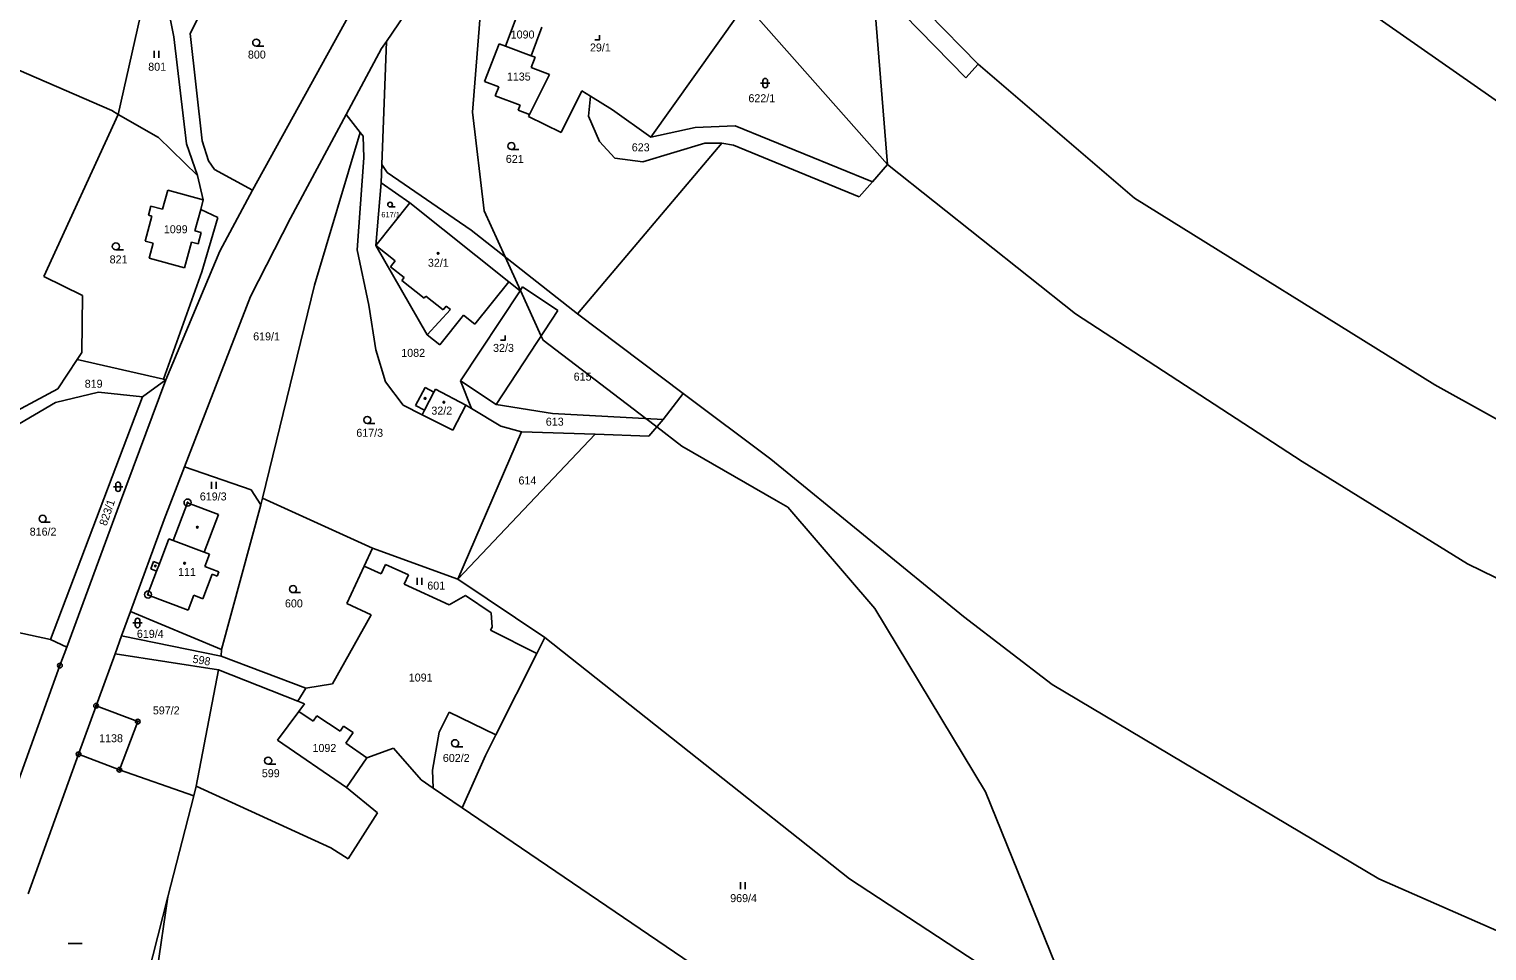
# Model space of a CAD drawing. Extents: x -547623 to -538651, y -1096714 to -1086522.
# Drawn here: x -542658.7 to -542349, y -1093298.3 to -1093102.4 of the extents above; entities that cross this region are included whole.
import ezdxf

# ---------------------------------------------------------------- set-up
doc = ezdxf.new("R2010")
doc.units = 0
for name, color, linetype in [('Vrstva 1', 7, 'Continuous'), ('Vrstva 25', 7, 'Continuous'), ('Vrstva 33', 7, 'Continuous'), ('Vrstva 52', 7, 'Continuous'), ('Vrstva 83', 7, 'Continuous'), ('Vrstva 86', 7, 'Continuous'), ('Vrstva 90', 7, 'Continuous'), ('Vrstva 92', 7, 'Continuous')]:
    doc.layers.add(name, color=color, linetype=linetype)

msp = doc.modelspace()

# ---------------------------------------------------------------- linework, layer by layer
at = {"layer": 'Vrstva 1'}
for points in [[(-542582.78, -1093104.99), (-542568.37, -1093083.76)], [(-542639.74, -1093120.53), (-542632.71, -1093089.02)], [(-542478.44, -1093087.92), (-542457.08, -1093109.85)], [(-542618.31, -1093091.02), (-542624.48, -1093103.34)], [(-542479.46, -1093092.45), (-542459.67, -1093112.74)], [(-542479.46, -1093092.45), (-542476.32, -1093131.19)], [(-542629.74, -1093094.66), (-542627.95, -1093104.03)], [(-542589.06, -1093096.44), (-542611.21, -1093136.61)], [(-542506.5, -1093097.1), (-542476.32, -1093131.19)], [(-542374.27, -1093098.54), (-542322.4, -1093134.78)], [(-542557.5, -1093105.98), (-542555.23, -1093099.95)], [(-542526.63, -1093125.33), (-542508, -1093099.2)], [(-542627.95, -1093104.03), (-542625.23, -1093126.8)], [(-542624.48, -1093103.34), (-542621.93, -1093126.14)], [(-542583.81, -1093106.51), (-542582.78, -1093104.99)], [(-542583.77, -1093131.16), (-542582.78, -1093104.99)], [(-542549.78, -1093102), (-542552.05, -1093108.03)], [(-542641.11, -1093119.69), (-542668.96, -1093107.67)], [(-542591.32, -1093120.51), (-542583.81, -1093106.51)], [(-542561.96, -1093113.49), (-542558.83, -1093105.48)], [(-542558.83, -1093105.48), (-542557.5, -1093105.98)], [(-542557.5, -1093105.98), (-542552.05, -1093108.03)], [(-542552.05, -1093108.03), (-542551.15, -1093108.37)], [(-542551.15, -1093108.37), (-542552, -1093110.55)], [(-542552, -1093110.55), (-542548.17, -1093112.05)], [(-542459.67, -1093112.74), (-542457.08, -1093109.85)], [(-542457.08, -1093109.85), (-542423.87, -1093138.3)], [(-542558.93, -1093114.65), (-542561.96, -1093113.49)], [(-542552.4, -1093120.52), (-542548.17, -1093112.05)], [(-542559.66, -1093116.54), (-542558.93, -1093114.65)], [(-542554.36, -1093118.57), (-542559.66, -1093116.54)], [(-542545.69, -1093124.39), (-542541.25, -1093115.51)], [(-542541.25, -1093115.51), (-542539.46, -1093116.62)], [(-542539.46, -1093116.62), (-542539.83, -1093120.87)], [(-542539.46, -1093116.62), (-542534.78, -1093119.51)], [(-542639.74, -1093120.53), (-542641.11, -1093119.69)], [(-542554.76, -1093119.61), (-542554.36, -1093118.57)], [(-542552.4, -1093120.52), (-542554.76, -1093119.61)], [(-542526.63, -1093125.33), (-542534.78, -1093119.51)], [(-542639.74, -1093120.53), (-542655.54, -1093154.96)], [(-542631.19, -1093125.39), (-542639.74, -1093120.53)], [(-542603.16, -1093142.57), (-542591.32, -1093120.51)], [(-542588.34, -1093124.34), (-542591.32, -1093120.51)], [(-542552.62, -1093120.95), (-542552.4, -1093120.52)], [(-542552.62, -1093120.95), (-542545.69, -1093124.39)], [(-542539.83, -1093120.87), (-542537.51, -1093126.26)], [(-542526.63, -1093125.33), (-542517.16, -1093123.27)], [(-542517.16, -1093123.27), (-542508.71, -1093122.95)], [(-542508.71, -1093122.95), (-542479.54, -1093134.83)], [(-542622.93, -1093133.52), (-542631.19, -1093125.39)], [(-542621.93, -1093126.14), (-542620.54, -1093130.39)], [(-542588.34, -1093124.34), (-542598.04, -1093156.8)], [(-542587.71, -1093125.15), (-542588.34, -1093124.34)], [(-542587.57, -1093129.75), (-542587.71, -1093125.15)], [(-542542.18, -1093162.93), (-542511.53, -1093126.62)], [(-542537.51, -1093126.26), (-542534.27, -1093129.8)], [(-542528.29, -1093130.61), (-542515.15, -1093126.64)], [(-542515.15, -1093126.64), (-542511.53, -1093126.62)], [(-542511.53, -1093126.62), (-542509.07, -1093127.05)], [(-542625.23, -1093126.8), (-542622.93, -1093133.52)], [(-542588.98, -1093149.31), (-542587.57, -1093129.75)], [(-542509.07, -1093127.05), (-542482.35, -1093138.01)], [(-542620.54, -1093130.39), (-542619.27, -1093132.2)], [(-542619.27, -1093132.2), (-542611.21, -1093136.61)], [(-542583.92, -1093135.06), (-542583.77, -1093131.16)], [(-542582.64, -1093132.89), (-542583.77, -1093131.16)], [(-542534.27, -1093129.8), (-542528.29, -1093130.61)], [(-542476.32, -1093131.19), (-542479.54, -1093134.83)], [(-542476.32, -1093131.19), (-542436.38, -1093162.87)], [(-542622.93, -1093133.52), (-542621.68, -1093138.69)], [(-542583.92, -1093135.06), (-542585.06, -1093148.36)], [(-542583.92, -1093135.06), (-542577.82, -1093139.29)], [(-542582.64, -1093132.89), (-542564.78, -1093145.08)], [(-542479.54, -1093134.83), (-542482.35, -1093138.01)], [(-542629.2, -1093136.62), (-542630.31, -1093140.67)], [(-542621.68, -1093138.69), (-542629.2, -1093136.62)], [(-542621.68, -1093138.69), (-542622.23, -1093140.71)], [(-542611.21, -1093136.61), (-542618.15, -1093149.57)], [(-542423.87, -1093138.3), (-542360.09, -1093178)], [(-542634.04, -1093147.42), (-542632.58, -1093142.12)], [(-542632.82, -1093139.98), (-542633.35, -1093141.91)], [(-542632.58, -1093142.12), (-542633.35, -1093141.91)], [(-542632.82, -1093139.98), (-542630.31, -1093140.67)], [(-542622.23, -1093140.71), (-542623.48, -1093145.25)], [(-542622.23, -1093140.71), (-542618.57, -1093142.43)], [(-542585.06, -1093148.36), (-542577.82, -1093139.29)], [(-542577.82, -1093139.29), (-542556.78, -1093156.1)], [(-542623.48, -1093145.25), (-542622.13, -1093145.62)], [(-542618.57, -1093142.43), (-542622.02, -1093153.97)], [(-542611.63, -1093159.23), (-542603.16, -1093142.57)], [(-542564.78, -1093145.08), (-542542.18, -1093162.93)], [(-542632.3, -1093147.9), (-542634.04, -1093147.42)], [(-542632.3, -1093147.9), (-542633.18, -1093151.08)], [(-542624.15, -1093147.66), (-542625.66, -1093153.15)], [(-542624.15, -1093147.66), (-542622.8, -1093148.03)], [(-542622.13, -1093145.62), (-542622.8, -1093148.03)], [(-542633.18, -1093151.08), (-542625.66, -1093153.15)], [(-542618.15, -1093149.57), (-542629.6, -1093176.91)], [(-542586.49, -1093161.06), (-542588.98, -1093149.31)], [(-542574.14, -1093167.36), (-542585.06, -1093148.36)], [(-542622.02, -1093153.97), (-542630.13, -1093176.79)], [(-542655.54, -1093154.96), (-542647.31, -1093158.99)], [(-542609.07, -1093202.06), (-542598.04, -1093156.8)], [(-542556.78, -1093156.1), (-542563.97, -1093165.09)], [(-542554.39, -1093158.02), (-542556.78, -1093156.1)], [(-542553.84, -1093157.19), (-542554.39, -1093158.02)], [(-542546.33, -1093162.17), (-542553.84, -1093157.19)], [(-542647.31, -1093158.99), (-542647.48, -1093171.08)], [(-542625.66, -1093195.44), (-542611.63, -1093159.23)], [(-542554.39, -1093158.02), (-542567.07, -1093177.14)], [(-542585.02, -1093170.55), (-542586.49, -1093161.06)], [(-542566.39, -1093163.17), (-542571.44, -1093169.51)], [(-542563.97, -1093165.09), (-542566.39, -1093163.17)], [(-542559.47, -1093182.18), (-542546.33, -1093162.17)], [(-542542.18, -1093162.93), (-542519.73, -1093179.82)], [(-542436.38, -1093162.87), (-542388.27, -1093194.28)], [(-542571.44, -1093169.51), (-542574.14, -1093167.36)], [(-542648.47, -1093172.57), (-542652.6, -1093178.82)], [(-542647.48, -1093171.08), (-542648.47, -1093172.57)], [(-542630.13, -1093176.79), (-542648.47, -1093172.57)], [(-542582.98, -1093177.36), (-542585.02, -1093170.55)], [(-542652.6, -1093178.82), (-542665.29, -1093185.66)], [(-542629.6, -1093176.91), (-542639.44, -1093203.32)], [(-542634.58, -1093180.54), (-542629.6, -1093176.91)], [(-542629.6, -1093176.91), (-542630.13, -1093176.79)], [(-542582.98, -1093177.36), (-542579.23, -1093182.28)], [(-542574.55, -1093178.53), (-542576.58, -1093182.39)], [(-542574.55, -1093178.53), (-542572.67, -1093179.52)], [(-542572.67, -1093179.52), (-542572.35, -1093178.92)], [(-542572.35, -1093178.92), (-542565.9, -1093182.31)], [(-542567.07, -1093177.14), (-542559.47, -1093182.18)], [(-542567.07, -1093177.14), (-542564.7, -1093183.03)], [(-542360.09, -1093178), (-542313.6, -1093203.8)], [(-542661.98, -1093186.96), (-542653.05, -1093181.73)], [(-542654.16, -1093232.09), (-542634.58, -1093180.54)], [(-542653.05, -1093181.73), (-542643.96, -1093179.58)], [(-542643.96, -1093179.58), (-542634.58, -1093180.54)], [(-542579.23, -1093182.28), (-542575.19, -1093184.33)], [(-542576.58, -1093182.39), (-542574.69, -1093183.39)], [(-542565.9, -1093182.31), (-542568.69, -1093187.63)], [(-542564.7, -1093183.03), (-542565.9, -1093182.31)], [(-542559.47, -1093182.18), (-542547.48, -1093184.06)], [(-542519.73, -1093179.82), (-542523.96, -1093185.36)], [(-542519.73, -1093179.82), (-542501.15, -1093193.8)], [(-542574.69, -1093183.39), (-542575.19, -1093184.33)], [(-542568.69, -1093187.63), (-542575.19, -1093184.33)], [(-542558.49, -1093186.77), (-542564.7, -1093183.03)], [(-542547.48, -1093184.06), (-542523.96, -1093185.36)], [(-542523.96, -1093185.36), (-542527.05, -1093188.87)], [(-542554.07, -1093188), (-542567.63, -1093219.3)], [(-542567.63, -1093219.3), (-542538.46, -1093188.5)], [(-542554.07, -1093188), (-542558.49, -1093186.77)], [(-542538.46, -1093188.5), (-542554.07, -1093188)], [(-542527.05, -1093188.87), (-542538.46, -1093188.5)], [(-542501.15, -1093193.8), (-542460.17, -1093227.19)], [(-542388.27, -1093194.28), (-542353.15, -1093216.05)], [(-542630, -1093206.63), (-542625.66, -1093195.44)], [(-542625.66, -1093195.44), (-542611.49, -1093200.3)], [(-542609.42, -1093203.5), (-542611.49, -1093200.3)], [(-542639.44, -1093203.32), (-542650.68, -1093233.73)], [(-542625.02, -1093203.05), (-542628.05, -1093211.04)], [(-542625.02, -1093203.05), (-542618.47, -1093205.53)], [(-542617.81, -1093234.23), (-542609.42, -1093203.5)], [(-542609.42, -1093203.5), (-542609.07, -1093202.06)], [(-542609.07, -1093202.06), (-542585.72, -1093212.69)], [(-542637.14, -1093226.17), (-542630, -1093206.63)], [(-542621.46, -1093213.54), (-542618.47, -1093205.53)], [(-542628.99, -1093210.69), (-542631.01, -1093216.01)], [(-542628.05, -1093211.04), (-542628.99, -1093210.69)], [(-542585.72, -1093212.69), (-542587.49, -1093216.51)], [(-542585.72, -1093212.69), (-542567.63, -1093219.3)], [(-542632.23, -1093215.55), (-542632.81, -1093217.09)], [(-542631.01, -1093216.01), (-542632.23, -1093215.55)], [(-542620.39, -1093213.95), (-542621.46, -1093213.54)], [(-542621.38, -1093216.57), (-542620.39, -1093213.95)], [(-542583.89, -1093218.16), (-542582.98, -1093216.18)], [(-542582.98, -1093216.18), (-542578.12, -1093218.4)], [(-542353.15, -1093216.05), (-542311.47, -1093236.33)], [(-542631.6, -1093217.56), (-542633.51, -1093222.6)], [(-542632.81, -1093217.09), (-542631.6, -1093217.56)], [(-542621.74, -1093223.44), (-542619.77, -1093218.25)], [(-542618.34, -1093217.72), (-542621.38, -1093216.57)], [(-542619.77, -1093218.25), (-542618.7, -1093218.66)], [(-542618.7, -1093218.66), (-542618.34, -1093217.72)], [(-542587.49, -1093216.51), (-542591.17, -1093224.46)], [(-542587.49, -1093216.51), (-542583.89, -1093218.16)], [(-542578.12, -1093218.4), (-542579.03, -1093220.38)], [(-542549.14, -1093231.71), (-542567.63, -1093219.3)], [(-542633.51, -1093222.6), (-542624.91, -1093225.87)], [(-542579.03, -1093220.38), (-542569.48, -1093224.75)], [(-542624.91, -1093225.87), (-542623.71, -1093222.69)], [(-542623.71, -1093222.69), (-542621.74, -1093223.44)], [(-542591.17, -1093224.46), (-542586.02, -1093226.84)], [(-542569.48, -1093224.75), (-542565.96, -1093222.75)], [(-542565.96, -1093222.75), (-542560.56, -1093226.45)], [(-542639.02, -1093231.34), (-542637.14, -1093226.17)], [(-542617.81, -1093234.23), (-542637.14, -1093226.17)], [(-542586.02, -1093226.84), (-542594.21, -1093241.57)], [(-542560.56, -1093226.45), (-542560.34, -1093229.49)], [(-542460.17, -1093227.19), (-542441.39, -1093241.7)], [(-542662.65, -1093230.29), (-542654.16, -1093232.09)], [(-542640.41, -1093235.14), (-542639.02, -1093231.34)], [(-542639.02, -1093231.34), (-542617.88, -1093235.65)], [(-542560.34, -1093229.49), (-542560.65, -1093230.12)], [(-542560.65, -1093230.12), (-542550.83, -1093235.06)], [(-542549.14, -1093231.71), (-542550.83, -1093235.06)], [(-542549.14, -1093231.71), (-542484.39, -1093283)], [(-542654.16, -1093232.09), (-542650.68, -1093233.73)], [(-542650.68, -1093233.73), (-542652.13, -1093237.64)], [(-542617.81, -1093234.23), (-542617.88, -1093235.65)], [(-542652.13, -1093237.64), (-542661.99, -1093265.04)], [(-542643.89, -1093244.67), (-542640.41, -1093235.14)], [(-542640.41, -1093235.14), (-542618.42, -1093238.59)], [(-542617.88, -1093235.65), (-542599.92, -1093242.47)], [(-542550.83, -1093235.06), (-542559.56, -1093252.41)], [(-542623.2, -1093263.32), (-542618.42, -1093238.59)], [(-542618.42, -1093238.59), (-542601.59, -1093245.21)], [(-542599.92, -1093242.47), (-542601.59, -1093245.21)], [(-542599.92, -1093242.47), (-542594.21, -1093241.57)], [(-542441.39, -1093241.7), (-542371.97, -1093282.96)], [(-542648.16, -1093256.49), (-542644.44, -1093246.2)], [(-542644.44, -1093246.2), (-542643.89, -1093244.67)], [(-542644.44, -1093246.2), (-542635.61, -1093249.57)], [(-542605.92, -1093253.48), (-542601.38, -1093247.39)], [(-542601.59, -1093245.21), (-542600.17, -1093245.77)], [(-542601.38, -1093247.39), (-542600.17, -1093245.77)], [(-542601.38, -1093247.39), (-542598.32, -1093249.47)], [(-542635.61, -1093249.57), (-542639.51, -1093259.79)], [(-542598.32, -1093249.47), (-542597.54, -1093248.31)], [(-542597.54, -1093248.31), (-542592.63, -1093251.59)], [(-542592.63, -1093251.59), (-542591.9, -1093250.52)], [(-542591.9, -1093250.52), (-542589.85, -1093251.85)], [(-542569.42, -1093247.53), (-542571.58, -1093251.82)], [(-542569.42, -1093247.53), (-542559.56, -1093252.41)], [(-542591.26, -1093263.54), (-542605.92, -1093253.48)], [(-542589.85, -1093251.85), (-542591.42, -1093254.17)], [(-542571.58, -1093251.82), (-542572.99, -1093259.85)], [(-542559.56, -1093252.41), (-542561.75, -1093256.77)], [(-542658.88, -1093286.15), (-542648.16, -1093256.49)], [(-542648.16, -1093256.49), (-542639.51, -1093259.79)], [(-542591.42, -1093254.17), (-542586.92, -1093257.23)], [(-542586.92, -1093257.23), (-542581.24, -1093255.23)], [(-542581.24, -1093255.23), (-542575.41, -1093261.97)], [(-542639.51, -1093259.79), (-542623.71, -1093265.33)], [(-542586.92, -1093257.23), (-542591.26, -1093263.54)], [(-542561.75, -1093256.77), (-542566.69, -1093267.9)], [(-542575.41, -1093261.97), (-542572.82, -1093263.73)], [(-542572.99, -1093259.85), (-542572.82, -1093263.73)], [(-542629.21, -1093286.81), (-542623.71, -1093265.33)], [(-542623.71, -1093265.33), (-542623.2, -1093263.32)], [(-542623.2, -1093263.32), (-542594.61, -1093276.38)], [(-542591.26, -1093263.54), (-542584.64, -1093268.96)], [(-542572.82, -1093263.73), (-542566.69, -1093267.9)], [(-542584.64, -1093268.96), (-542590.92, -1093278.71)], [(-542566.69, -1093267.9), (-542474.7, -1093330.48)], [(-542594.61, -1093276.38), (-542590.92, -1093278.71)], [(-542484.39, -1093283), (-542430.15, -1093318.56)], [(-542371.97, -1093282.96), (-542337.64, -1093298.09)], [(-542629.21, -1093286.81), (-542640.95, -1093333.05)], [(-542633.91, -1093318.82), (-542629.21, -1093286.81)]]:
    msp.add_lwpolyline(points, dxfattribs=at)
at = {"layer": 'Vrstva 25'}
for p, q in [((-542632.09, -1093108.48), (-542632.09, -1093106.98)), ((-542631.09, -1093108.48), (-542631.09, -1093106.98)), ((-542610.43, -1093106), (-542608.83, -1093106)), ((-542503.31, -1093113.85), (-542501.31, -1093113.85)), ((-542502.81, -1093114.35), (-542502.81, -1093113.35)), ((-542501.81, -1093113.35), (-542501.81, -1093114.35)), ((-542556.23, -1093127.99), (-542554.63, -1093127.99)), ((-542581.99, -1093140.18), (-542580.92, -1093140.18)), ((-542640.25, -1093149.31), (-542638.65, -1093149.31)), ((-542586.84, -1093186.21), (-542585.24, -1093186.21)), ((-542640.77, -1093199.64), (-542638.77, -1093199.64)), ((-542640.27, -1093200.14), (-542640.27, -1093199.14)), ((-542639.27, -1093199.14), (-542639.27, -1093200.14)), ((-542619.93, -1093200.09), (-542619.93, -1093198.59)), ((-542618.93, -1093200.09), (-542618.93, -1093198.59)), ((-542655.8, -1093207.21), (-542654.2, -1093207.21)), ((-542576.24, -1093220.48), (-542576.24, -1093218.98)), ((-542575.24, -1093220.48), (-542575.24, -1093218.98)), ((-542602.61, -1093222.15), (-542601.01, -1093222.15)), ((-542636.64, -1093228.6), (-542634.64, -1093228.6)), ((-542636.14, -1093229.1), (-542636.14, -1093228.1)), ((-542635.14, -1093228.1), (-542635.14, -1093229.1)), ((-542568.18, -1093254.91), (-542566.58, -1093254.91)), ((-542607.9, -1093258.62), (-542606.3, -1093258.62)), ((-542507.55, -1093285.2), (-542507.55, -1093283.7)), ((-542506.55, -1093285.2), (-542506.55, -1093283.7)), ((-542650.37, -1093296.75), (-542647.37, -1093296.75))]:
    msp.add_line(p, q, dxfattribs=at)
for points in [[(-542538.49, -1093104.66), (-542537.49, -1093104.66), (-542537.49, -1093103.66)], [(-542558.56, -1093168.5), (-542557.56, -1093168.5), (-542557.56, -1093167.5)]]:
    msp.add_lwpolyline(points, dxfattribs=at)
for centre, radius in [((-542610.43, -1093105.25), 0.75), ((-542556.23, -1093127.24), 0.75), ((-542581.99, -1093139.68), 0.503), ((-542640.25, -1093148.56), 0.75), ((-542571.79, -1093150.04), 0.175), ((-542574.55, -1093180.88), 0.175), ((-542570.58, -1093181.68), 0.175), ((-542586.84, -1093185.46), 0.75), ((-542655.8, -1093206.46), 0.75), ((-542622.94, -1093208.25), 0.175), ((-542631.87, -1093216.5), 0.175), ((-542625.66, -1093215.9), 0.175), ((-542602.61, -1093221.4), 0.75), ((-542568.18, -1093254.16), 0.75), ((-542607.9, -1093257.87), 0.75)]:
    msp.add_circle(centre, radius, dxfattribs=at)
for centre, start, end in [((-542502.31, -1093113.35), 0, 180), ((-542502.31, -1093114.35), 180, 0), ((-542639.77, -1093199.14), 0, 180), ((-542639.77, -1093200.14), 180, 0), ((-542635.64, -1093228.1), 0, 180), ((-542635.64, -1093229.1), 180, 0)]:
    msp.add_arc(centre, 0.5, start, end, dxfattribs=at)
at = {"layer": 'Vrstva 33'}
for points in [[(-542580.92, -1093151.64), (-542585.06, -1093148.36)], [(-542581.91, -1093152.89), (-542580.92, -1093151.64)], [(-542579.02, -1093155.19), (-542581.91, -1093152.89)], [(-542579.52, -1093155.81), (-542579.02, -1093155.19)], [(-542574.75, -1093159.59), (-542579.52, -1093155.81)], [(-542574.38, -1093159.12), (-542574.75, -1093159.59)], [(-542570.71, -1093162.03), (-542574.38, -1093159.12)], [(-542574.14, -1093167.36), (-542569.15, -1093162)], [(-542570.09, -1093161.25), (-542570.71, -1093162.03)], [(-542569.15, -1093162), (-542570.09, -1093161.25)], [(-542574.69, -1093183.39), (-542572.67, -1093179.52)], [(-542628.05, -1093211.04), (-542621.46, -1093213.54)], [(-542631.6, -1093217.56), (-542631.01, -1093216.01)]]:
    msp.add_lwpolyline(points, dxfattribs=at)
at = {"layer": 'Vrstva 52'}
msp.add_lwpolyline([(-542562.06, -1093089.73), (-542564.5, -1093120), (-542562, -1093141), (-542557.55, -1093150.79), (-542554.31, -1093157.91), (-542549.9, -1093167.61), (-542549.5, -1093168.5), (-542527.66, -1093185.16), (-542525.34, -1093186.93), (-542520, -1093191), (-542500, -1093202.56), (-542497.5, -1093204), (-542479, -1093225.5), (-542455.5, -1093264.5), (-542439.5, -1093304), (-542436.71, -1093314.26), (-542434.24, -1093323.35), (-542428.5, -1093344.5), (-542425.25, -1093373.75), (-542423, -1093394), (-542422.7, -1093435.17), (-542422.67, -1093437.9), (-542422.65, -1093441.62), (-542422.36, -1093480.32)], dxfattribs=at)
at = {"layer": 'Vrstva 83'}
for centre, radius in [((-542625.02, -1093203.01), 0.75), ((-542625.02, -1093203.01), 0.1), ((-542633.41, -1093222.55), 0.75), ((-542633.41, -1093222.55), 0.1), ((-542652.13, -1093237.64), 0.5), ((-542652.13, -1093237.64), 0.1), ((-542644.44, -1093246.2), 0.5), ((-542644.44, -1093246.2), 0.1), ((-542635.61, -1093249.57), 0.5), ((-542635.61, -1093249.57), 0.1), ((-542648.16, -1093256.49), 0.5), ((-542648.16, -1093256.49), 0.1), ((-542639.51, -1093259.79), 0.5), ((-542639.51, -1093259.79), 0.1)]:
    msp.add_circle(centre, radius, dxfattribs=at)
at = {"layer": 'Vrstva 90'}
for points in [[(-542585.06, -1093148.36), (-542577.82, -1093139.29)], [(-542577.82, -1093139.29), (-542556.78, -1093156.1)], [(-542580.92, -1093151.64), (-542585.06, -1093148.36)], [(-542581.91, -1093152.89), (-542580.92, -1093151.64)], [(-542579.02, -1093155.19), (-542581.91, -1093152.89)], [(-542579.52, -1093155.81), (-542579.02, -1093155.19)], [(-542574.75, -1093159.59), (-542579.52, -1093155.81)], [(-542556.78, -1093156.1), (-542563.97, -1093165.09)], [(-542574.38, -1093159.12), (-542574.75, -1093159.59)], [(-542570.71, -1093162.03), (-542574.38, -1093159.12)], [(-542574.14, -1093167.36), (-542569.15, -1093162)], [(-542566.39, -1093163.17), (-542571.44, -1093169.51)], [(-542570.09, -1093161.25), (-542570.71, -1093162.03)], [(-542569.15, -1093162), (-542570.09, -1093161.25)], [(-542563.97, -1093165.09), (-542566.39, -1093163.17)], [(-542571.44, -1093169.51), (-542574.14, -1093167.36)], [(-542572.67, -1093179.52), (-542572.35, -1093178.92)], [(-542572.35, -1093178.92), (-542565.9, -1093182.31)], [(-542574.69, -1093183.39), (-542572.67, -1093179.52)], [(-542565.9, -1093182.31), (-542568.69, -1093187.63)], [(-542574.69, -1093183.39), (-542575.19, -1093184.33)], [(-542568.69, -1093187.63), (-542575.19, -1093184.33)], [(-542628.99, -1093210.69), (-542631.01, -1093216.01)], [(-542628.05, -1093211.04), (-542628.99, -1093210.69)], [(-542628.05, -1093211.04), (-542621.46, -1093213.54)], [(-542631.6, -1093217.56), (-542631.01, -1093216.01)], [(-542620.39, -1093213.95), (-542621.46, -1093213.54)], [(-542621.38, -1093216.57), (-542620.39, -1093213.95)], [(-542631.6, -1093217.56), (-542633.51, -1093222.6)], [(-542621.74, -1093223.44), (-542619.77, -1093218.25)], [(-542618.34, -1093217.72), (-542621.38, -1093216.57)], [(-542619.77, -1093218.25), (-542618.7, -1093218.66)], [(-542618.7, -1093218.66), (-542618.34, -1093217.72)], [(-542633.51, -1093222.6), (-542624.91, -1093225.87)], [(-542624.91, -1093225.87), (-542623.71, -1093222.69)], [(-542623.71, -1093222.69), (-542621.74, -1093223.44)]]:
    msp.add_lwpolyline(points, dxfattribs=at)

# ---------------------------------------------------------------- texts
at = {"layer": 'Vrstva 86'}
for s, height, p in [('1090', 1.7, (-542556.38, -1093104.38)), ('800', 1.7, (-542612.2, -1093108.64)), ('801', 1.7, (-542633.37, -1093111.23)), ('1135', 1.7, (-542557.19, -1093113.32)), ('622/1', 1.7, (-542505.88, -1093117.92)), ('623', 1.7, (-542530.66, -1093128.36)), ('621', 1.7, (-542557.41, -1093130.82)), ('617/1', 1.14, (-542583.85, -1093142.39)), ('1099', 1.7, (-542630.06, -1093145.77)), ('821', 1.7, (-542641.57, -1093152.18)), ('619/1', 1.7, (-542611.08, -1093168.54)), ('1082', 1.7, (-542579.62, -1093172.04)), ('615', 1.7, (-542543, -1093177.1)), ('819', 1.7, (-542646.86, -1093178.6)), ('613', 1.7, (-542548.92, -1093186.67)), ('617/3', 1.7, (-542589.17, -1093189.03)), ('614', 1.7, (-542554.72, -1093199.16)), ('619/3', 1.7, (-542622.41, -1093202.56)), ('816/2', 1.7, (-542658.55, -1093210.04)), ('601', 1.7, (-542574.09, -1093221.51)), ('600', 1.7, (-542604.33, -1093225.29)), ('619/4', 1.7, (-542635.78, -1093231.76)), ('1091', 1.7, (-542578.03, -1093241.05)), ('597/2', 1.7, (-542632.39, -1093248.03)), ('1138', 1.7, (-542643.8, -1093253.95)), ('1092', 1.7, (-542598.48, -1093256.02)), ('602/2', 1.7, (-542570.79, -1093258.14)), ('599', 1.7, (-542609.24, -1093261.38)), ('969/4', 1.7, (-542509.75, -1093287.93))]:
    msp.add_text(s, height=height, dxfattribs=at).set_placement(p)
for s, rotation, p in [('823/1', 71.1616, (-542642.24, -1093208.09)), ('598', 350.079, (-542624.05, -1093237.02))]:
    msp.add_text(s, height=1.7, rotation=rotation, dxfattribs=at).set_placement(p)
at = {"layer": 'Vrstva 92'}
for s, p in [('29/1', (-542539.54, -1093107.14)), ('32/1', (-542573.96, -1093152.89)), ('32/3', (-542560.12, -1093170.99)), ('32/2', (-542573.23, -1093184.32)), ('111', (-542627.03, -1093218.61))]:
    msp.add_text(s, height=1.7, dxfattribs=at).set_placement(p)

doc.saveas('drawing.dxf')
